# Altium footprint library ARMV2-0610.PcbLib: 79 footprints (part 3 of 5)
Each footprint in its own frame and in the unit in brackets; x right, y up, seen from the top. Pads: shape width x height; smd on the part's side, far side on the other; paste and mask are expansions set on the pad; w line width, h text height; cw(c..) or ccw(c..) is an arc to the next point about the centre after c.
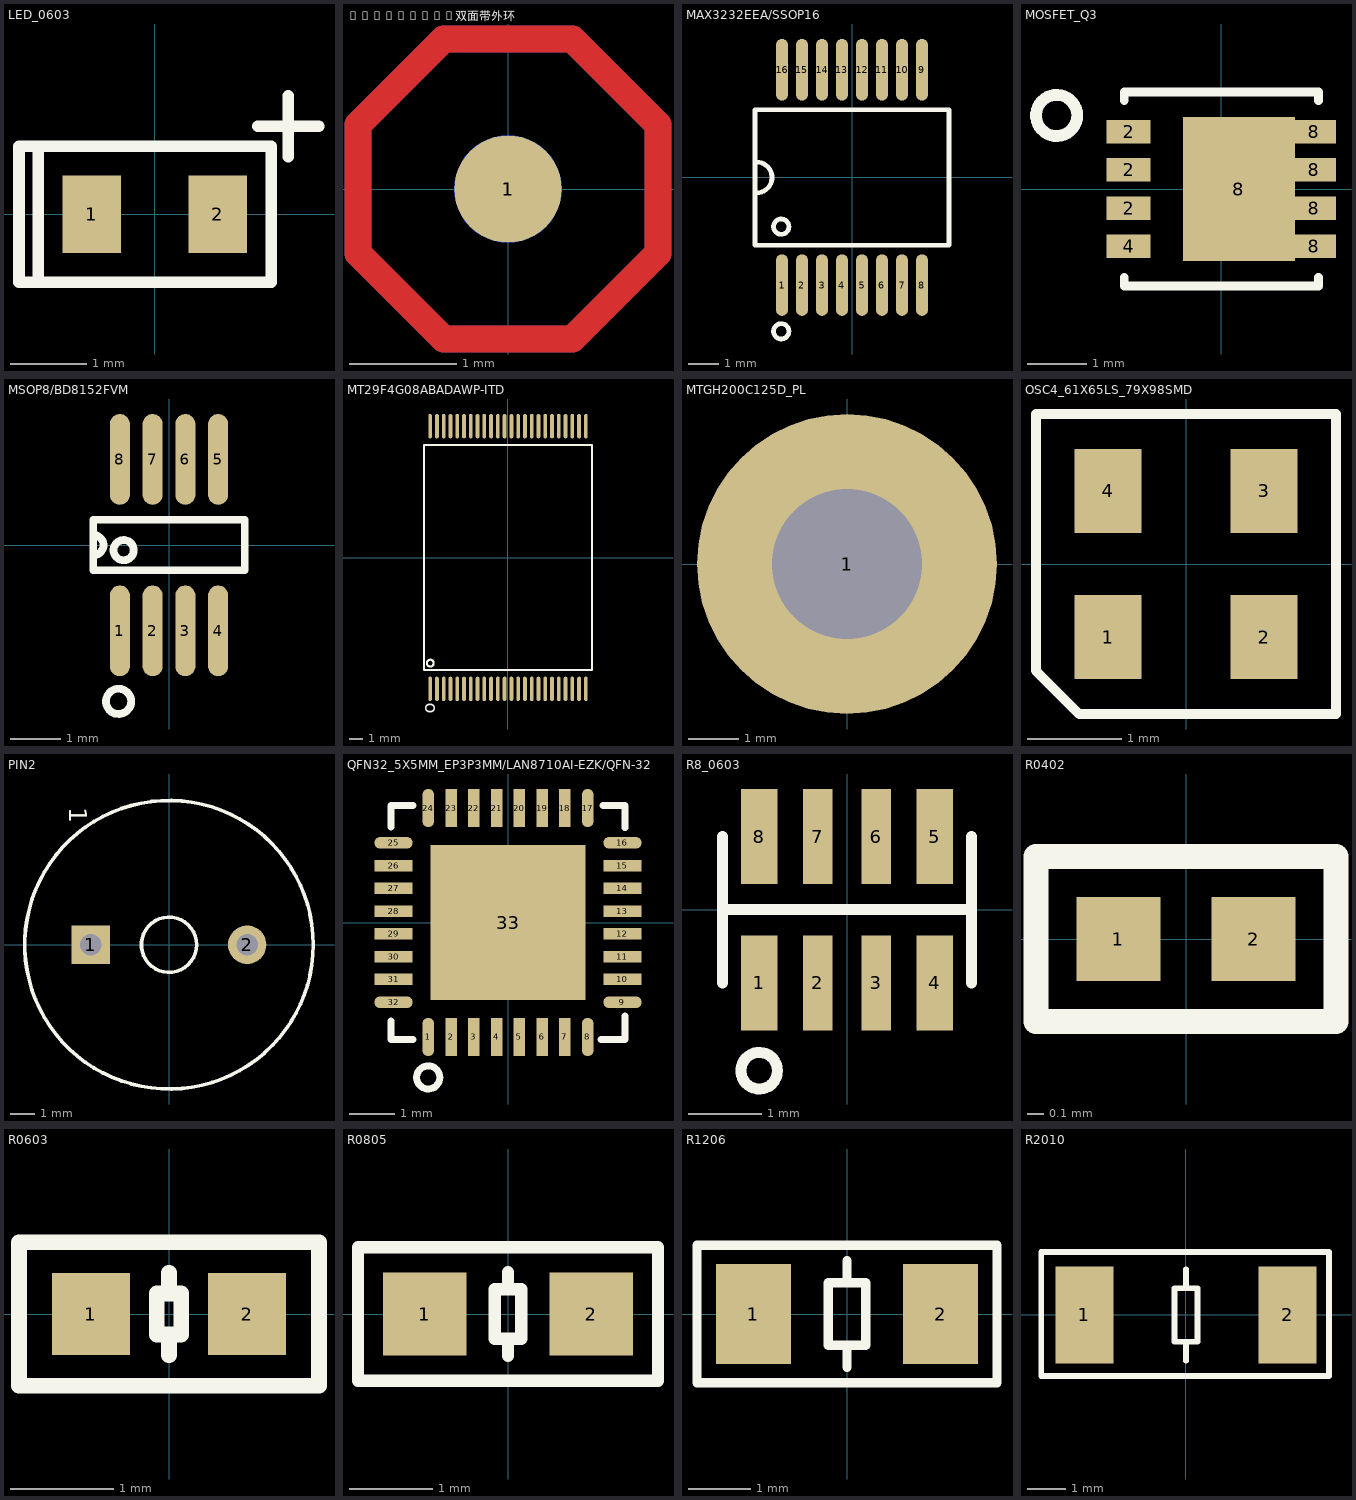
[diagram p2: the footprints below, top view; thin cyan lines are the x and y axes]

## LED_0603 [mil] "LED_0603"
pads (2):
  rect 30x40 smd mask+2: 1(-32.5,0) 2(32.5,0)
Top Overlay:
  lines w5.91: 53.15,45.28 84.65,45.28 ; 68.9,29.53 68.9,61.02
  lines w6: -60,-35 -60,35 ; -60,-35 -70,-35 -70,35 -60,35 ; -60,-35 -60,35 ; -60,-35 60,-35 60,35 -60,35

## MARK_PCB_双面带外环 [mm]
height 0.762
pads (2):
  round 1 smd far side mask+0.5: 1(0,0)
  round 1 smd mask+0.5: 1(0,0)
Top Layer:
  lines w0.254: -1.4,-0.6 -1.4,0.6 -0.6,1.4 0.6,1.4 1.4,0.6 1.4,-0.6 0.6,-1.4 -0.6,-1.4 -1.4,-0.6
Bottom Layer:
  lines w0.254: -1.4,-0.6 -1.4,0.6 -0.6,1.4 0.6,1.4 1.4,0.6 1.4,-0.6 0.6,-1.4 -0.6,-1.4 -1.4,-0.6

## MAX3232EEA/SSOP16 [mm]
pads (16):
  oval 0.4x2 smd: 1(-2.275,-3.5) 2(-1.625,-3.5) 3(-0.975,-3.5) 4(-0.325,-3.5) 5(0.325,-3.5) 6(0.975,-3.5) 7(1.625,-3.5) 8(2.275,-3.5) 9(2.275,3.5) 10(1.625,3.5) 11(0.975,3.5) 12(0.325,3.5) 13(-0.325,3.5) 14(-0.975,3.5) 15(-1.625,3.5) 16(-2.275,3.5)
Top Overlay:
  circle w0.152: c-2.3,-5 r0.25
  circle w0.152: c-2.3,-1.6 r0.25
  lines w0.152: -3.1,-0.5 ccw(c-3.1,0) -3.1,0.5 ; -3.15,-2.2 -3.15,2.2 3.15,2.2 3.15,-2.2 -3.15,-2.2

## MOSFET_Q3 [mm]
pads (9):
  rect 0.75x0.4 smd: 2(-1.575,-0.325) 2(-1.575,0.325) 2(-1.575,0.975) 4(-1.575,-0.975) 8(1.575,-0.975) 8(1.575,-0.325) 8(1.575,0.325) 8(1.575,0.975)
  rect 1.9x2.45 smd: 8(0.3,0)
Top Overlay:
  circle w0.2: c-2.8,1.25 r0.35
  lines w0.152: -1.65,-1.5 -1.65,-1.65 1.65,-1.65 1.65,-1.5 ; -1.65,1.5 -1.65,1.65 1.65,1.65 1.65,1.5

## MSOP8/BD8152FVM [mm]
pads (8):
  oval 0.4x1.8 smd: 1(-0.975,-1.7) 2(-0.325,-1.7) 3(0.325,-1.7) 4(0.975,-1.7) 5(0.975,1.7) 6(0.325,1.7) 7(-0.325,1.7) 8(-0.975,1.7)
Top Overlay:
  circle w0.152: c-0.9,-0.1 r0.2
  circle w0.152: c-1,-3.1 r0.25
  lines w0.152: -1.5,-0.2 ccw(c-1.5,0) -1.5,0.2 ; -1.5,-0.5 1.5,-0.5 1.5,0.5 -1.5,0.5 -1.5,-0.5

## MT29F4G08ABADAWP-ITD [mm]
pads (48):
  oval 0.28x1.8 smd: 1(-5.75,-9.7) 2(-5.25,-9.7) 3(-4.75,-9.7) 4(-4.25,-9.7) 5(-3.75,-9.7) 6(-3.25,-9.7) 7(-2.75,-9.7) 8(-2.25,-9.7) 9(-1.75,-9.7) 10(-1.25,-9.7) 11(-0.75,-9.7) 12(-0.25,-9.7) 13(0.25,-9.7) 14(0.75,-9.7) 15(1.25,-9.7) 16(1.75,-9.7) 17(2.25,-9.7) 18(2.75,-9.7) 19(3.25,-9.7) 20(3.75,-9.7) 21(4.25,-9.7) 22(4.75,-9.7) 23(5.25,-9.7) 24(5.75,-9.7) 25(5.75,9.7) 26(5.25,9.7) 27(4.75,9.7) 28(4.25,9.7) 29(3.75,9.7) 30(3.25,9.7) 31(2.75,9.7) 32(2.25,9.7) 33(1.75,9.7) 34(1.25,9.7) 35(0.75,9.7) 36(0.25,9.7) 37(-0.25,9.7) 38(-0.75,9.7) 39(-1.25,9.7) 40(-1.75,9.7) 41(-2.25,9.7) 42(-2.75,9.7) 43(-3.25,9.7) 44(-3.75,9.7) 45(-4.25,9.7) 46(-4.75,9.7) 47(-5.25,9.7) 48(-5.75,9.7)
Top Overlay:
  circle w0.152: c-5.74,-7.798 r0.254
  lines w0.15: -6.2,-8.3 -6.2,8.3 6.2,8.3 6.2,-8.3 -6.2,-8.3
  text "o" at -5.359,-11.557 h0.98

## MTGH200C125D_PL [mm] "MTGH200C125D_PL"
pads (1):
  round 6 hole 3 mask+0.051: 1(0,0)

## OSC4_61X65LS_79X98SMD [mil] "OSC4_61X65LS_79X98SMD"
pads (4):
  rect 28x35 smd mask+2: 1(-32.5,-30.5) 2(32.5,-30.5) 3(32.5,30.5) 4(-32.5,30.5)
Top Overlay:
  lines w4: -62.5,-44.5 -44.5,-62.5 62.5,-62.5 62.5,62.5 -62.5,62.5 -62.5,-44.5

## PIN2 [mm]
height 8.5
pads (2):
  rect 1.6x1.6 hole 0.9: 1(-3.25,0)
  round 1.6 hole 0.9: 2(3.25,0)
Top Overlay:
  circle w0.152: c0,0 r6
  circle w0.152: c0,0 r1.15
  text "1" at -4.14,5.715 h0.76

## QFN32_5X5MM_EP3P3MM/LAN8710AI-EZK/QFN-32 [mil]
height 39.37
pads (33):
  oval 10x33 smd mask+2: 1(-68.95,-99) 8(68.95,-99) 17(68.95,99) 24(-68.95,99)
  rect 10x33 smd mask+2: 2(-49.25,-99) 3(-29.55,-99) 4(-9.85,-99) 5(9.85,-99) 6(29.55,-99) 7(49.25,-99) 18(49.25,99) 19(29.55,99) 20(9.85,99) 21(-9.85,99) 22(-29.55,99) 23(-49.25,99)
  oval 33x10 smd mask+2: 9(99,-68.95) 16(99,68.95) 25(-99,68.95) 32(-99,-68.95)
  rect 33x10 smd mask+2: 10(99,-49.25) 11(99,-29.55) 12(99,-9.85) 13(99,9.85) 14(99,29.55) 15(99,49.25) 26(-99,49.25) 27(-99,29.55) 28(-99,9.85) 29(-99,-9.85) 30(-99,-29.55) 31(-99,-49.25)
  rect 134x134 smd mask+2: 33(0,0)
Top Overlay:
  circle w6: c-69,-134 r10
  lines w6: -101.29,-85 -101.29,-101.29 -82,-101.29 ; -101.29,82.5 -101.29,101.29 -82,101.29 ; 80.5,-101.29 101.29,-101.29 101.29,-81 ; 82,101.29 101.29,101.29 101.29,82

## R8_0603 [mm]
pads (8):
  rect 0.5x1.3 smd: 1(-1.2,-1) 4(1.2,-1) 5(1.2,1) 8(-1.2,1)
  rect 0.4x1.3 smd: 2(-0.4,-1) 3(0.4,-1) 6(0.4,1) 7(-0.4,1)
Top Overlay:
  circle w0.15: c-1.2,-2.2 r0.25
  lines w0.15: -1.7,-1 -1.7,1 ; -1.7,0 1.7,0 ; 1.7,-1 1.7,1

## R0402 [mm]
height 0.4
pads (2):
  rect 0.51x0.51 smd: 1(-0.41,0) 2(0.41,0)
Top Overlay:
  lines w0.152: -0.91,-0.5 0.91,-0.5 0.91,0.5 -0.91,0.5 -0.91,-0.5

## R0603 [mm]
height 0.6
pads (2):
  rect 0.76x0.8 smd: 1(-0.76,0) 2(0.76,0)
Top Overlay:
  lines w0.152: 0,-0.4 0,-0.2 ; 0,0.2 0,0.4 ; -1.46,-0.7 -1.46,0.7 1.46,0.7 1.46,-0.7 -1.46,-0.7 ; -0.12,-0.2 0.12,-0.2 0.12,0.2 -0.12,0.2 -0.12,-0.2

## R0805 [mm]
height 0.65
pads (2):
  rect 1x1 smd: 1(-1,0) 2(1,0)
Top Overlay:
  lines w0.15: 0,-0.5 0,-0.3 ; 0,0.3 0,0.5 ; -1.8,-0.8 -1.8,0.8 1.8,0.8 1.8,-0.8 -1.8,-0.8 ; -0.16,-0.3 -0.16,0.3 0.16,0.3 0.16,-0.3 -0.16,-0.3

## R1206 [mm]
height 0.71
pads (2):
  rect 1.2x1.6 smd: 1(-1.5,0) 2(1.5,0)
Top Overlay:
  lines w0.15: 0,-0.85 0,-0.5 ; 0,0.5 0,0.85 ; -2.4,-1.1 -2.4,1.1 2.4,1.1 2.4,-1.1 -2.4,-1.1 ; -0.3,-0.5 0.3,-0.5 0.3,0.5 -0.3,0.5 -0.3,-0.5

## R2010 [mm] "R2010"
pads (2):
  rect 1.52x2.54 smd: 1(-2.665,0) 2(2.665,0)
Top Overlay:
  lines w0.15: 0,-1.2 0,-0.7 ; 0,0.7 0,1.2 ; 3.7,1.65 -3.8,1.65 -3.8,-1.6 3.75,-1.6 3.75,1.65 ; -0.3,-0.7 0.3,-0.7 0.3,0.7 -0.3,0.7 -0.3,-0.7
